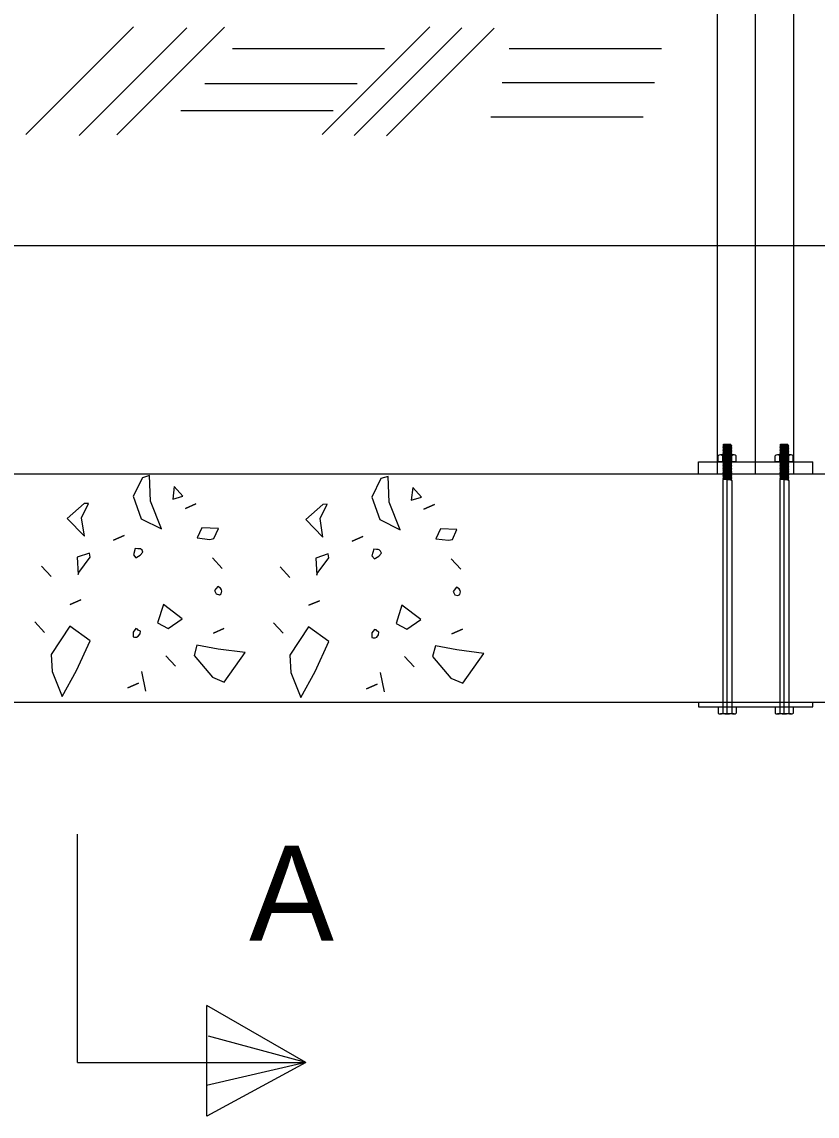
# Model space of a CAD drawing. Extents: x 0 to 90.7, y 0 to 62.8.
# Drawn here: x 32.44 to 35.923, y 33.053 to 37.844 of the extents above; entities that cross this region are included whole.
import ezdxf

# ---------------------------------------------------------------- set-up
doc = ezdxf.new("R2010")
doc.units = 0
for name, color, linetype in [('BRDG_ANNO_General-Notes', 7, 'Continuous'), ('BRDG_BASE_Ground-Lines', 7, 'Continuous'), ('BRDG_BASE_Hidden-Line', 7, 'Continuous'), ('BRDG_BASE_Obj-Line', 7, 'Continuous'), ('BRDG_BASE_Pattern', 7, 'Continuous')]:
    doc.layers.add(name, color=color, linetype=linetype)

msp = doc.modelspace()

# ---------------------------------------------------------------- linework, layer by layer
at = {"layer": 'BRDG_BASE_Ground-Lines'}
for p, q in [((32.9292, 37.823), (32.4578, 37.3516)), ((33.1619, 37.8181), (32.6905, 37.3467)), ((33.3274, 37.8205), (32.856, 37.3491)), ((34.2266, 37.823), (33.7552, 37.3516)), ((34.3669, 37.818), (33.8955, 37.3466)), ((34.5088, 37.8172), (34.0374, 37.3458)), ((33.3617, 37.727), (34.0283, 37.727)), ((34.574, 37.727), (35.2407, 37.727)), ((33.2415, 37.5742), (33.9081, 37.5742)), ((34.544, 37.5792), (35.2106, 37.5792)), ((33.1362, 37.4565), (33.8029, 37.4565)), ((34.4939, 37.4289), (35.1605, 37.4289))]:
    msp.add_line(p, q, dxfattribs=at)
at = {"layer": 'BRDG_BASE_Hidden-Line'}
for p, q in [((35.529, 35.9683), (35.529, 35.9167)), ((35.529, 35.9484), (35.529, 35.9183)), ((35.7789, 35.9683), (35.7789, 35.9167)), ((35.7789, 35.9484), (35.7789, 35.9183)), ((35.529, 34.8139), (35.529, 34.844)), ((35.7789, 34.8139), (35.7789, 34.844))]:
    msp.add_line(p, q, dxfattribs=at)
at = {"layer": 'BRDG_BASE_Obj-Line'}
for p, q in [((35.6534, 35.8655), (35.6534, 40.2405)), ((35.4868, 35.8655), (35.4868, 38.9905)), ((35.8201, 35.8655), (35.8201, 38.9905)), ((26.9455, 36.8655), (38.6534, 36.8655)), ((35.5142, 35.9939), (35.5092, 35.9906)), ((35.5444, 35.9935), (35.5092, 35.9906)), ((35.5142, 35.9873), (35.5092, 35.9906)), ((35.5142, 35.9873), (35.5092, 35.984)), ((35.5488, 35.9873), (35.5092, 35.984)), ((35.5142, 35.9807), (35.5092, 35.984)), ((35.5439, 35.9939), (35.5142, 35.9939)), ((35.5439, 35.9906), (35.5142, 35.9873)), ((35.5439, 35.984), (35.5142, 35.9807)), ((35.5439, 35.9939), (35.5464, 35.9922)), ((35.5439, 35.9906), (35.5464, 35.9922)), ((35.5439, 35.9906), (35.5488, 35.9873)), ((35.5439, 35.984), (35.5488, 35.9873)), ((35.5439, 35.984), (35.5488, 35.9807)), ((35.7641, 35.9939), (35.7591, 35.9906)), ((35.7943, 35.9935), (35.7591, 35.9906)), ((35.7641, 35.9873), (35.7591, 35.9906)), ((35.7641, 35.9873), (35.7591, 35.984)), ((35.7987, 35.9873), (35.7591, 35.984)), ((35.7641, 35.9807), (35.7591, 35.984)), ((35.7937, 35.9939), (35.7641, 35.9939)), ((35.7937, 35.9906), (35.7641, 35.9873)), ((35.7937, 35.984), (35.7641, 35.9807)), ((35.7937, 35.9939), (35.7963, 35.9922)), ((35.7937, 35.9906), (35.7963, 35.9922)), ((35.7937, 35.9906), (35.7987, 35.9873)), ((35.7937, 35.984), (35.7987, 35.9873)), ((35.7937, 35.984), (35.7987, 35.9807)), ((35.4894, 35.9203), (35.4894, 35.9446)), ((35.559, 35.9483), (35.4993, 35.9483)), ((35.5142, 35.9807), (35.5092, 35.9774)), ((35.5488, 35.9807), (35.5092, 35.9774)), ((35.5142, 35.9741), (35.5092, 35.9774)), ((35.5142, 35.9741), (35.5092, 35.9708)), ((35.5488, 35.9741), (35.5092, 35.9708)), ((35.5142, 35.9676), (35.5092, 35.9708)), ((35.5142, 35.9676), (35.5092, 35.9642)), ((35.5488, 35.9676), (35.5092, 35.9642)), ((35.5142, 35.9609), (35.5092, 35.9642)), ((35.5142, 35.9609), (35.5092, 35.9577)), ((35.5488, 35.9609), (35.5092, 35.9577)), ((35.5142, 35.9543), (35.5092, 35.9577)), ((35.5142, 35.9543), (35.5092, 35.951)), ((35.5488, 35.9543), (35.5092, 35.951)), ((35.5142, 35.9478), (35.5092, 35.951)), ((35.5142, 35.9478), (35.5092, 35.9444)), ((35.5488, 35.9478), (35.5092, 35.9444)), ((35.5092, 35.9183), (35.5092, 35.9446)), ((35.5142, 35.9411), (35.5092, 35.9444)), ((35.5142, 35.9411), (35.5092, 35.9379)), ((35.5488, 35.9411), (35.5092, 35.9379)), ((35.5142, 35.9345), (35.5092, 35.9379)), ((35.5439, 35.9774), (35.5142, 35.9741)), ((35.5439, 35.9708), (35.5142, 35.9676)), ((35.5439, 35.9642), (35.5142, 35.9609)), ((35.5439, 35.9577), (35.5142, 35.9543)), ((35.5439, 35.951), (35.5142, 35.9478)), ((35.5439, 35.9444), (35.5142, 35.9411)), ((35.5439, 35.9379), (35.5142, 35.9345)), ((35.5439, 35.9774), (35.5488, 35.9807)), ((35.5439, 35.9774), (35.5488, 35.9741)), ((35.5439, 35.9708), (35.5488, 35.9741)), ((35.5439, 35.9708), (35.5488, 35.9676)), ((35.5439, 35.9642), (35.5488, 35.9676)), ((35.5439, 35.9642), (35.5488, 35.9609)), ((35.5439, 35.9577), (35.5488, 35.9609)), ((35.5439, 35.9577), (35.5488, 35.9543)), ((35.5439, 35.951), (35.5488, 35.9543)), ((35.5439, 35.951), (35.5488, 35.9478)), ((35.5439, 35.9444), (35.5488, 35.9478)), ((35.5439, 35.9444), (35.5488, 35.9411)), ((35.5439, 35.9379), (35.5488, 35.9411)), ((35.5439, 35.9379), (35.5488, 35.9345)), ((35.5488, 35.9184), (35.5488, 35.9446)), ((35.5686, 35.9203), (35.5686, 35.9446)), ((35.7393, 35.9203), (35.7393, 35.9446)), ((35.8089, 35.9483), (35.7492, 35.9483)), ((35.7641, 35.9807), (35.7591, 35.9774)), ((35.7987, 35.9807), (35.7591, 35.9774)), ((35.7641, 35.9741), (35.7591, 35.9774)), ((35.7641, 35.9741), (35.7591, 35.9708)), ((35.7987, 35.9741), (35.7591, 35.9708)), ((35.7641, 35.9676), (35.7591, 35.9708)), ((35.7641, 35.9676), (35.7591, 35.9642)), ((35.7987, 35.9676), (35.7591, 35.9642)), ((35.7641, 35.9609), (35.7591, 35.9642)), ((35.7641, 35.9609), (35.7591, 35.9577)), ((35.7987, 35.9609), (35.7591, 35.9577)), ((35.7641, 35.9543), (35.7591, 35.9577)), ((35.7641, 35.9543), (35.7591, 35.951)), ((35.7987, 35.9543), (35.7591, 35.951)), ((35.7641, 35.9478), (35.7591, 35.951)), ((35.7641, 35.9478), (35.7591, 35.9444)), ((35.7987, 35.9478), (35.7591, 35.9444)), ((35.7591, 35.9183), (35.7591, 35.9446)), ((35.7641, 35.9411), (35.7591, 35.9444)), ((35.7641, 35.9411), (35.7591, 35.9379)), ((35.7987, 35.9411), (35.7591, 35.9379)), ((35.7641, 35.9345), (35.7591, 35.9379)), ((35.7937, 35.9774), (35.7641, 35.9741)), ((35.7937, 35.9708), (35.7641, 35.9676)), ((35.7937, 35.9642), (35.7641, 35.9609)), ((35.7937, 35.9577), (35.7641, 35.9543)), ((35.7937, 35.951), (35.7641, 35.9478)), ((35.7937, 35.9444), (35.7641, 35.9411)), ((35.7937, 35.9379), (35.7641, 35.9345)), ((35.7937, 35.9774), (35.7987, 35.9807)), ((35.7937, 35.9774), (35.7987, 35.9741)), ((35.7937, 35.9708), (35.7987, 35.9741)), ((35.7937, 35.9708), (35.7987, 35.9676)), ((35.7937, 35.9642), (35.7987, 35.9676)), ((35.7937, 35.9642), (35.7987, 35.9609)), ((35.7937, 35.9577), (35.7987, 35.9609)), ((35.7937, 35.9577), (35.7987, 35.9543)), ((35.7937, 35.951), (35.7987, 35.9543)), ((35.7937, 35.951), (35.7987, 35.9478)), ((35.7937, 35.9444), (35.7987, 35.9478)), ((35.7937, 35.9444), (35.7987, 35.9411)), ((35.7937, 35.9379), (35.7987, 35.9411)), ((35.7937, 35.9379), (35.7987, 35.9345)), ((35.7987, 35.9184), (35.7987, 35.9446)), ((35.8185, 35.9203), (35.8185, 35.9446)), ((35.4034, 35.9176), (35.9034, 35.9176)), ((35.4034, 35.8655), (35.4034, 35.9176)), ((35.5666, 35.9183), (35.4914, 35.9183)), ((35.5142, 35.9345), (35.5092, 35.9312)), ((35.5488, 35.9345), (35.5092, 35.9312)), ((35.5142, 35.928), (35.5092, 35.9312)), ((35.5142, 35.928), (35.5092, 35.9246)), ((35.5488, 35.928), (35.5092, 35.9246)), ((35.5142, 35.9213), (35.5092, 35.9246)), ((35.5142, 35.9213), (35.5092, 35.9181)), ((35.5488, 35.9213), (35.5092, 35.9181)), ((35.5142, 35.9147), (35.5092, 35.9181)), ((35.5142, 35.9147), (35.5092, 35.9114)), ((35.5488, 35.9147), (35.5092, 35.9114)), ((35.5142, 35.9082), (35.5092, 35.9114)), ((35.5142, 35.9082), (35.5092, 35.9048)), ((35.5488, 35.9082), (35.5092, 35.9048)), ((35.5142, 35.9015), (35.5092, 35.9048)), ((35.5142, 35.9015), (35.5092, 35.8983)), ((35.5488, 35.9015), (35.5092, 35.8983)), ((35.5142, 35.8949), (35.5092, 35.8983)), ((35.5142, 35.8949), (35.5092, 35.8916)), ((35.5488, 35.8949), (35.5092, 35.8916)), ((35.5142, 35.8884), (35.5092, 35.8916)), ((35.5142, 35.8884), (35.5092, 35.8851)), ((35.5488, 35.8884), (35.5092, 35.8851)), ((35.5439, 35.9312), (35.5142, 35.928)), ((35.5439, 35.9246), (35.5142, 35.9213)), ((35.5439, 35.9181), (35.5142, 35.9147)), ((35.5439, 35.9114), (35.5142, 35.9082)), ((35.5439, 35.9048), (35.5142, 35.9015)), ((35.5439, 35.8983), (35.5142, 35.8949)), ((35.5439, 35.8916), (35.5142, 35.8884)), ((35.5284, 34.8447), (35.5284, 35.9176)), ((35.5439, 35.9312), (35.5488, 35.9345)), ((35.5439, 35.9312), (35.5488, 35.928)), ((35.5439, 35.9246), (35.5488, 35.928)), ((35.5439, 35.9246), (35.5488, 35.9213)), ((35.5439, 35.9181), (35.5488, 35.9213)), ((35.5439, 35.9181), (35.5488, 35.9147)), ((35.5439, 35.9114), (35.5488, 35.9147)), ((35.5439, 35.9114), (35.5488, 35.9082)), ((35.5439, 35.9048), (35.5488, 35.9082)), ((35.5439, 35.9048), (35.5488, 35.9015)), ((35.5439, 35.8983), (35.5488, 35.9015)), ((35.5439, 35.8983), (35.5488, 35.8949)), ((35.5439, 35.8916), (35.5488, 35.8949)), ((35.5439, 35.8916), (35.5488, 35.8884)), ((35.5439, 35.8851), (35.5488, 35.8884)), ((35.8165, 35.9183), (35.7413, 35.9183)), ((35.7641, 35.9345), (35.7591, 35.9312)), ((35.7987, 35.9345), (35.7591, 35.9312)), ((35.7641, 35.928), (35.7591, 35.9312)), ((35.7641, 35.928), (35.7591, 35.9246)), ((35.7987, 35.928), (35.7591, 35.9246)), ((35.7641, 35.9213), (35.7591, 35.9246)), ((35.7641, 35.9213), (35.7591, 35.9181)), ((35.7987, 35.9213), (35.7591, 35.9181)), ((35.7641, 35.9147), (35.7591, 35.9181)), ((35.7641, 35.9147), (35.7591, 35.9114)), ((35.7987, 35.9147), (35.7591, 35.9114)), ((35.7641, 35.9082), (35.7591, 35.9114)), ((35.7641, 35.9082), (35.7591, 35.9048)), ((35.7987, 35.9082), (35.7591, 35.9048)), ((35.7641, 35.9015), (35.7591, 35.9048)), ((35.7641, 35.9015), (35.7591, 35.8983)), ((35.7987, 35.9015), (35.7591, 35.8983)), ((35.7641, 35.8949), (35.7591, 35.8983)), ((35.7641, 35.8949), (35.7591, 35.8916)), ((35.7987, 35.8949), (35.7591, 35.8916)), ((35.7641, 35.8884), (35.7591, 35.8916)), ((35.7641, 35.8884), (35.7591, 35.8851)), ((35.7987, 35.8884), (35.7591, 35.8851)), ((35.7937, 35.9312), (35.7641, 35.928)), ((35.7937, 35.9246), (35.7641, 35.9213)), ((35.7937, 35.9181), (35.7641, 35.9147)), ((35.7937, 35.9114), (35.7641, 35.9082)), ((35.7937, 35.9048), (35.7641, 35.9015)), ((35.7937, 35.8983), (35.7641, 35.8949)), ((35.7937, 35.8916), (35.7641, 35.8884)), ((35.7784, 34.8447), (35.7784, 35.9176)), ((35.7937, 35.9312), (35.7987, 35.9345)), ((35.7937, 35.9312), (35.7987, 35.928)), ((35.7937, 35.9246), (35.7987, 35.928)), ((35.7937, 35.9246), (35.7987, 35.9213)), ((35.7937, 35.9181), (35.7987, 35.9213)), ((35.7937, 35.9181), (35.7987, 35.9147)), ((35.7937, 35.9114), (35.7987, 35.9147)), ((35.7937, 35.9114), (35.7987, 35.9082)), ((35.7937, 35.9048), (35.7987, 35.9082)), ((35.7937, 35.9048), (35.7987, 35.9015)), ((35.7937, 35.8983), (35.7987, 35.9015)), ((35.7937, 35.8983), (35.7987, 35.8949)), ((35.7937, 35.8916), (35.7987, 35.8949)), ((35.7937, 35.8916), (35.7987, 35.8884)), ((35.7937, 35.8851), (35.7987, 35.8884)), ((35.9034, 35.8655), (35.9034, 35.9176)), ((26.9455, 35.8655), (38.6534, 35.8655)), ((35.5142, 35.8817), (35.5092, 35.8851)), ((35.5142, 35.8817), (35.5092, 35.8785)), ((35.5488, 35.8817), (35.5092, 35.8785)), ((35.5142, 35.8752), (35.5092, 35.8785)), ((35.5142, 35.8752), (35.5092, 35.8718)), ((35.5488, 35.8752), (35.5092, 35.8718)), ((35.5142, 35.8686), (35.5092, 35.8718)), ((35.5142, 35.8686), (35.5092, 35.8653)), ((35.5488, 35.8686), (35.5092, 35.8653)), ((35.5142, 35.8619), (35.5092, 35.8653)), ((35.5142, 35.8619), (35.5092, 35.8587)), ((35.5488, 35.8619), (35.5092, 35.8587)), ((35.5142, 35.8554), (35.5092, 35.8587)), ((35.5142, 35.8554), (35.5092, 35.852)), ((35.5488, 35.8554), (35.5092, 35.852)), ((35.5142, 35.8488), (35.5092, 35.852)), ((35.5142, 35.8488), (35.5092, 35.8455)), ((35.5488, 35.8488), (35.5092, 35.8455)), ((35.5142, 35.8421), (35.5092, 35.8455)), ((35.5142, 35.8421), (35.5092, 35.8389)), ((35.5488, 35.8421), (35.5092, 35.8389)), ((35.5439, 35.8851), (35.5142, 35.8817)), ((35.5439, 35.8785), (35.5142, 35.8752)), ((35.5439, 35.8718), (35.5142, 35.8686)), ((35.5439, 35.8653), (35.5142, 35.8619)), ((35.5439, 35.8587), (35.5142, 35.8554)), ((35.5439, 35.852), (35.5142, 35.8488)), ((35.5439, 35.8455), (35.5142, 35.8421)), ((35.5439, 35.8851), (35.5488, 35.8817)), ((35.5439, 35.8785), (35.5488, 35.8817)), ((35.5439, 35.8785), (35.5488, 35.8752)), ((35.5439, 35.8718), (35.5488, 35.8752)), ((35.5439, 35.8718), (35.5488, 35.8686)), ((35.5439, 35.8653), (35.5488, 35.8686)), ((35.5439, 35.8653), (35.5488, 35.8619)), ((35.5439, 35.8587), (35.5488, 35.8619)), ((35.5439, 35.8587), (35.5488, 35.8554)), ((35.5439, 35.852), (35.5488, 35.8554)), ((35.5439, 35.852), (35.5488, 35.8488)), ((35.5439, 35.8455), (35.5488, 35.8488)), ((35.5439, 35.8455), (35.5488, 35.8421)), ((35.5439, 35.8389), (35.5488, 35.8421)), ((35.7641, 35.8817), (35.7591, 35.8851)), ((35.7641, 35.8817), (35.7591, 35.8785)), ((35.7987, 35.8817), (35.7591, 35.8785)), ((35.7641, 35.8752), (35.7591, 35.8785)), ((35.7641, 35.8752), (35.7591, 35.8718)), ((35.7987, 35.8752), (35.7591, 35.8718)), ((35.7641, 35.8686), (35.7591, 35.8718)), ((35.7641, 35.8686), (35.7591, 35.8653)), ((35.7987, 35.8686), (35.7591, 35.8653)), ((35.7641, 35.8619), (35.7591, 35.8653)), ((35.7641, 35.8619), (35.7591, 35.8587)), ((35.7987, 35.8619), (35.7591, 35.8587)), ((35.7641, 35.8554), (35.7591, 35.8587)), ((35.7641, 35.8554), (35.7591, 35.852)), ((35.7987, 35.8554), (35.7591, 35.852)), ((35.7641, 35.8488), (35.7591, 35.852)), ((35.7641, 35.8488), (35.7591, 35.8455)), ((35.7987, 35.8488), (35.7591, 35.8455)), ((35.7641, 35.8421), (35.7591, 35.8455)), ((35.7641, 35.8421), (35.7591, 35.8389)), ((35.7987, 35.8421), (35.7591, 35.8389)), ((35.7937, 35.8851), (35.7641, 35.8817)), ((35.7937, 35.8785), (35.7641, 35.8752)), ((35.7937, 35.8718), (35.7641, 35.8686)), ((35.7937, 35.8653), (35.7641, 35.8619)), ((35.7937, 35.8587), (35.7641, 35.8554)), ((35.7937, 35.852), (35.7641, 35.8488)), ((35.7937, 35.8455), (35.7641, 35.8421)), ((35.7937, 35.8851), (35.7987, 35.8817)), ((35.7937, 35.8785), (35.7987, 35.8817)), ((35.7937, 35.8785), (35.7987, 35.8752)), ((35.7937, 35.8718), (35.7987, 35.8752)), ((35.7937, 35.8718), (35.7987, 35.8686)), ((35.7937, 35.8653), (35.7987, 35.8686)), ((35.7937, 35.8653), (35.7987, 35.8619)), ((35.7937, 35.8587), (35.7987, 35.8619)), ((35.7937, 35.8587), (35.7987, 35.8554)), ((35.7937, 35.852), (35.7987, 35.8554)), ((35.7937, 35.852), (35.7987, 35.8488)), ((35.7937, 35.8455), (35.7987, 35.8488)), ((35.7937, 35.8455), (35.7987, 35.8421)), ((35.7937, 35.8389), (35.7987, 35.8421)), ((35.5092, 35.8389), (35.5092, 34.844)), ((35.5439, 35.8389), (35.5291, 35.8372)), ((35.5439, 35.8389), (35.5488, 35.8356)), ((35.5488, 35.8356), (35.5488, 34.8439)), ((35.7591, 35.8389), (35.7591, 34.844)), ((35.7937, 35.8389), (35.779, 35.8372)), ((35.7937, 35.8389), (35.7987, 35.8356)), ((35.7987, 35.8356), (35.7987, 34.8439)), ((26.9455, 34.8655), (36.6534, 34.8655)), ((35.4034, 34.8655), (35.4034, 34.8447)), ((35.4034, 34.8447), (35.9034, 34.8447)), ((35.4894, 34.842), (35.4894, 34.8177)), ((35.5666, 34.844), (35.4914, 34.844)), ((35.5092, 34.844), (35.5092, 34.8177)), ((35.5488, 34.8439), (35.5488, 34.8177)), ((35.5686, 34.842), (35.5686, 34.8177)), ((35.7393, 34.842), (35.7393, 34.8177)), ((35.8165, 34.844), (35.7413, 34.844)), ((35.7591, 34.844), (35.7591, 34.8177)), ((35.7987, 34.8439), (35.7987, 34.8177)), ((35.8185, 34.842), (35.8185, 34.8177)), ((35.9034, 34.8447), (35.9034, 34.8655)), ((35.559, 34.814), (35.4993, 34.814)), ((35.8089, 34.814), (35.7492, 34.814)), ((32.6836, 33.2875), (32.6836, 34.2875)), ((33.6836, 33.2875), (33.2506, 33.5375)), ((33.2506, 33.0529), (33.2506, 33.5375)), ((33.6836, 33.2875), (33.2574, 33.4033)), ((32.6836, 33.2875), (33.6836, 33.2875)), ((33.6836, 33.2875), (33.2483, 33.1867)), ((33.6836, 33.2875), (33.2506, 33.0529))]:
    msp.add_line(p, q, dxfattribs=at)
for centre, radius, start, end in [((35.4993, 35.9326), 0.0157, 50.7833, 129.2167), ((35.529, 35.8933), 0.055, 68.9268, 111.0732), ((35.5587, 35.9326), 0.0157, 50.7833, 129.2167), ((35.7492, 35.9326), 0.0157, 50.7833, 129.2167), ((35.7789, 35.8933), 0.055, 68.9268, 111.0732), ((35.8086, 35.9326), 0.0157, 50.7833, 129.2167), ((35.4914, 35.9203), 0.00198, 180, 270), ((35.5666, 35.9203), 0.00198, 270, 0), ((35.7413, 35.9203), 0.00198, 180, 270), ((35.8165, 35.9203), 0.00198, 270, 0), ((35.4914, 34.842), 0.00198, 90, 180), ((35.5666, 34.842), 0.00198, 0, 90), ((35.7413, 34.842), 0.00198, 90, 180), ((35.8165, 34.842), 0.00198, 0, 90), ((35.4993, 34.8297), 0.0157, 230.7833, 309.2167), ((35.529, 34.869), 0.055, 248.9268, 291.0732), ((35.5587, 34.8297), 0.0157, 230.7833, 309.2167), ((35.7492, 34.8297), 0.0157, 230.7833, 309.2167), ((35.7789, 34.869), 0.055, 248.9268, 291.0732), ((35.8086, 34.8297), 0.0157, 230.7833, 309.2167)]:
    msp.add_arc(centre, radius, start, end, dxfattribs=at)
at = {"layer": 'BRDG_BASE_Pattern'}
for p, q in [((32.5258, 35.4611), (32.5683, 35.4154)), ((33.2748, 35.4969), (33.3172, 35.451)), ((33.5708, 35.4576), (33.6133, 35.4118)), ((34.3197, 35.4932), (34.3622, 35.4474)), ((32.497, 35.2166), (32.5394, 35.1709)), ((33.5419, 35.213), (33.5844, 35.1672)), ((33.0706, 35.0689), (33.113, 35.0231)), ((34.1156, 35.0653), (34.158, 35.0195)), ((32.9644, 34.9997), (32.982, 34.9136)), ((34.0093, 34.9961), (34.0269, 34.91))]:
    msp.add_line(p, q, dxfattribs=at)
for points in [[(32.9676, 35.848), (32.9277, 35.767), (32.9623, 35.6682), (33.0521, 35.6238), (33.0032, 35.7449), (32.9987, 35.8578)], [(34.0126, 35.8444), (33.9727, 35.7634), (34.0072, 35.6646), (34.097, 35.6202), (34.0481, 35.7413), (34.0436, 35.8542)], [(33.1071, 35.8095), (33.1004, 35.7544), (33.1448, 35.7668)], [(34.152, 35.8059), (34.1454, 35.7507), (34.1897, 35.7632)], [(32.7131, 35.7349), (32.6386, 35.6695), (32.7137, 35.592), (32.7007, 35.6732), (32.7319, 35.7359)], [(33.1558, 35.714), (33.2018, 35.7342)], [(33.7581, 35.7314), (33.6836, 35.6658), (33.7586, 35.5884), (33.7457, 35.6696), (33.7768, 35.7323)], [(34.2007, 35.7104), (34.2468, 35.7306)], [(33.2279, 35.6285), (33.2081, 35.585), (33.2633, 35.5783), (33.2805, 35.5818), (33.3003, 35.6254)], [(34.2728, 35.6249), (34.253, 35.5814), (34.3083, 35.5747), (34.3255, 35.5782), (34.3453, 35.6218)], [(32.8414, 35.5745), (32.8875, 35.5946)], [(33.8863, 35.5709), (33.9324, 35.591)], [(32.682, 35.4999), (32.6867, 35.4251), (32.6887, 35.4327), (32.7396, 35.5008), (32.736, 35.5181)], [(32.9358, 35.5389), (32.9281, 35.5102), (32.9387, 35.4974), (32.9435, 35.5002), (32.9579, 35.5085), (32.9696, 35.5216), (32.9661, 35.5307), (32.9595, 35.5365), (32.9557, 35.5376), (32.9476, 35.5375)], [(33.7269, 35.4964), (33.7316, 35.4215), (33.7336, 35.4291), (33.7845, 35.4972), (33.781, 35.5145)], [(33.9807, 35.5353), (33.973, 35.5066), (33.9836, 35.4938), (33.9884, 35.4966), (34.0029, 35.5049), (34.0145, 35.518), (34.011, 35.5271), (34.0045, 35.5329), (34.0007, 35.5339), (33.9926, 35.5339)], [(33.2984, 35.3725), (33.2831, 35.3541), (33.2914, 35.3396), (33.3049, 35.336), (33.3123, 35.3403), (33.3154, 35.3517), (33.3148, 35.3578), (33.3105, 35.3652)], [(34.3433, 35.3689), (34.3281, 35.3505), (34.3364, 35.336), (34.3498, 35.3324), (34.3573, 35.3367), (34.3604, 35.3481), (34.3597, 35.3542), (34.3555, 35.3616)], [(32.6521, 35.2931), (32.6982, 35.3133)], [(33.0595, 35.2938), (33.0338, 35.2134), (33.0802, 35.1887), (33.1424, 35.2309)], [(33.697, 35.2895), (33.7431, 35.3097)], [(34.1044, 35.2902), (34.0787, 35.2097), (34.1251, 35.1851), (34.1874, 35.2273)], [(32.6505, 35.1989), (32.5679, 35.0742), (32.5727, 34.9996), (32.6167, 34.8902), (32.6795, 35.0036), (32.739, 35.1344)], [(32.9271, 35.1724), (32.9279, 35.1519), (32.9334, 35.1504), (32.9416, 35.1505), (32.9489, 35.1544), (32.9574, 35.1643), (32.9588, 35.1761), (32.9497, 35.1808), (32.9469, 35.1856), (32.9393, 35.1876)], [(33.2784, 35.1682), (33.3245, 35.1884)], [(33.6954, 35.1953), (33.6129, 35.0706), (33.6177, 34.996), (33.6616, 34.8866), (33.7244, 35), (33.7839, 35.1308)], [(33.9721, 35.1688), (33.9728, 35.1483), (33.9783, 35.1468), (33.9865, 35.1469), (33.9939, 35.1508), (34.0023, 35.1607), (34.0037, 35.1725), (33.9946, 35.1772), (33.9918, 35.182), (33.9843, 35.184)], [(34.3234, 35.1645), (34.3694, 35.1848)], [(33.2993, 35.0982), (33.206, 35.1151), (33.1939, 35.0695), (33.2743, 34.9747), (33.3257, 34.9528), (33.4175, 35.0828)], [(34.3442, 35.0946), (34.251, 35.1115), (34.2388, 35.0659), (34.3192, 34.9711), (34.3707, 34.9492), (34.4624, 35.0792)], [(32.9045, 34.9281), (32.9506, 34.9483)], [(33.9495, 34.9245), (33.9956, 34.9447)]]:
    msp.add_lwpolyline(points, close=True, dxfattribs=at)

# ---------------------------------------------------------------- texts
at = {"layer": 'BRDG_ANNO_General-Notes'}
msp.add_text('A', height=0.4167, dxfattribs=at).set_placement((33.4349, 33.8211))

doc.saveas('drawing.dxf')
